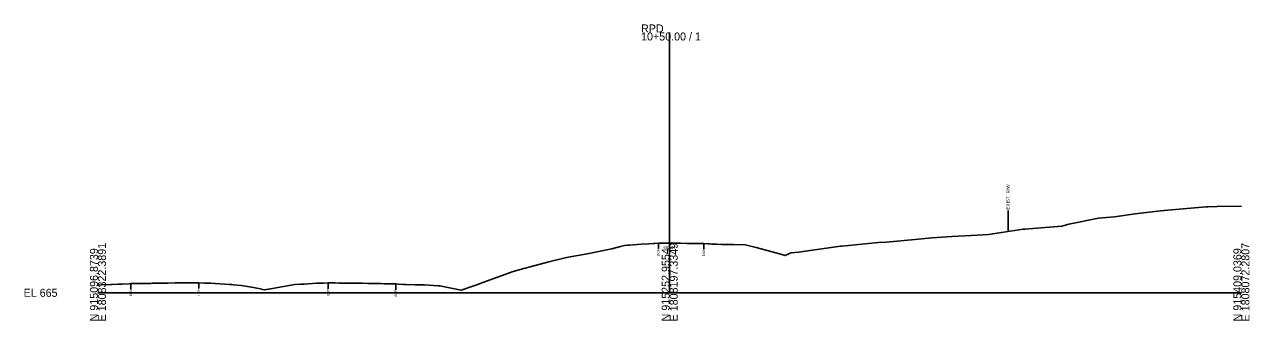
# Model space of a CAD drawing. Extents: x -26 to 403, y -10 to 8517.
# Drawn here: x -25.7 to 402.8, y 990.3 to 1093.9 of the extents above; entities that cross this region are included whole.
import ezdxf

# ---------------------------------------------------------------- set-up
doc = ezdxf.new("R2010")
doc.units = 0
for name, color, linetype in [('Exist Cross Section Cell', 7, 'Continuous'), ('Exist XS Center Line Elevation Label', 7, 'Continuous'), ('Exist XS Ground Line', 7, 'Continuous'), ('Old_Level_10', 7, 'Continuous')]:
    doc.layers.add(name, color=color, linetype=linetype)

msp = doc.modelspace()

# ---------------------------------------------------------------- linework, layer by layer
at = {"layer": 'Exist Cross Section Cell'}
for p, q in [((200, 1000), (200, 1091.12)), ((0, 1000), (200, 1000)), ((200, 1000), (400, 1000))]:
    msp.add_line(p, q, dxfattribs=at)
at = {"layer": 'Exist XS Ground Line'}
msp.add_lwpolyline([(0, 1002.72), (1.41, 1002.79), (4.47, 1002.94), (5, 1002.95), (6.97, 1003.02), (8.46, 1003.06), (10.95, 1003.18), (11.55, 1003.22), (14.93, 1003.27), (16.69, 1003.31), (18.09, 1003.32), (18.47, 1003.32), (18.92, 1003.33), (21.27, 1003.36), (23.06, 1003.38), (23.41, 1003.39), (23.84, 1003.4), (24.49, 1003.41), (26.99, 1003.44), (27.36, 1003.45), (27.66, 1003.45), (29.14, 1003.47), (30.97, 1003.49), (34.06, 1003.51), (34.9, 1003.53), (35.24, 1003.53), (37.3, 1003.43), (38.01, 1003.43), (38.47, 1003.43), (39.46, 1003.41), (40.98, 1003.29), (44.4, 1003.05), (45.99, 1002.93), (46.85, 1002.87), (47.42, 1002.82), (50.11, 1002.62), (52.96, 1002.1), (56.29, 1001.5), (58.13, 1001.05), (60.43, 1001.45), (62.96, 1001.87), (68.88, 1002.88), (70.91, 1003), (72.14, 1003.08), (76.45, 1003.37), (78.96, 1003.39), (80.56, 1003.47), (82.11, 1003.45), (82.95, 1003.44), (84.27, 1003.43), (85.33, 1003.42), (86.92, 1003.4), (88.57, 1003.38), (90.94, 1003.35), (91.52, 1003.34), (92.58, 1003.33), (94.61, 1003.29), (94.96, 1003.28), (96.73, 1003.25), (98.12, 1003.23), (98.95, 1003.22), (100.28, 1003.19), (101.34, 1003.17), (102.05, 1003.15), (102.96, 1003.14), (104.19, 1003.12), (105.01, 1003.04), (106.92, 1002.94), (107.72, 1002.91), (110.94, 1002.82), (113.83, 1002.75), (114.18, 1002.74), (119.04, 1002.47), (119.71, 1002.44), (121.21, 1002.13), (127.08, 1000.94), (131.18, 1002.34), (132.14, 1002.69), (133.67, 1003.23), (144.96, 1007.34), (147.76, 1008.21), (157.77, 1010.83), (163.94, 1012.31), (164.44, 1012.43), (170.59, 1013.58), (179.74, 1015.44), (182.85, 1016.24), (184.25, 1016.56), (185.25, 1016.63), (185.96, 1016.68), (190.08, 1016.99), (192.69, 1017.19), (194.29, 1017.25), (194.8, 1017.29), (196.07, 1017.4), (197.47, 1017.39), (198.09, 1017.39), (198.88, 1017.38), (200, 1017.37), (200.66, 1017.37), (202.89, 1017.35), (203.83, 1017.35), (206.17, 1017.31), (207.06, 1017.29), (207.82, 1017.28), (210.26, 1017.24), (210.68, 1017.24), (212, 1017.22), (213.5, 1017.12), (214.09, 1017.09), (214.8, 1017.06), (216.4, 1016.98), (218.16, 1016.94), (220.22, 1016.9), (221.5, 1016.87), (222.37, 1016.86), (226.4, 1016.79), (230.21, 1015.87), (238.4, 1013.61), (240.45, 1013.02), (241.87, 1013.82), (242.52, 1013.95), (245.19, 1014.27), (247.47, 1014.61), (259.71, 1016.3), (260.28, 1016.37), (262.59, 1016.57), (273.1, 1017.58), (275.7, 1017.73), (285.91, 1018.69), (291.7, 1019.23), (298.72, 1019.69), (307.69, 1020.16), (311.54, 1020.41), (323.68, 1022.24), (324.35, 1022.32), (327.05, 1022.57), (337.16, 1023.37), (339.68, 1024.05), (349.98, 1026.1), (355.67, 1026.6), (362.79, 1027.59), (371.66, 1028.66), (375.61, 1029.02), (387.65, 1030.06), (388.42, 1030.1), (391.51, 1030.17), (400, 1030.37)], dxfattribs=at)
at = {"layer": 'Old_Level_10'}
for p, q in [((318.36, 1028.84), (318.36, 1021.44)), ((196.07, 1017.4), (196.07, 1015.35)), ((212, 1017.22), (212, 1015.17)), ((11.55, 1003.22), (11.55, 1001.17)), ((35.24, 1003.53), (35.24, 1001.48)), ((80.56, 1003.47), (80.56, 1001.42)), ((104.19, 1003.12), (104.19, 1001.07))]:
    msp.add_line(p, q, dxfattribs=at)

# ---------------------------------------------------------------- texts
at = {"layer": 'Exist Cross Section Cell'}
for s, p in [('RPD', (190, 1091.12)), ('10+50.00 / 1', (190, 1088.32)), ('EL 665', (-26, 998.6))]:
    msp.add_text(s, height=2.8, dxfattribs=at).set_placement(p)
for s, p in [('E 1808322.3891', (2.8, 990)), ('E 1808197.3349', (202.8, 990)), ('E 1808072.2807', (402.8, 990)), ('N 915096.8739', (0, 990)), ('N 915252.9554', (200, 990)), ('N 915409.0369', (400, 990))]:
    msp.add_text(s, height=2.8, rotation=90, dxfattribs=at).set_placement(p)
at = {"layer": 'Exist XS Center Line Elevation Label'}
msp.add_text('682.37', height=1, dxfattribs=at).set_placement((197.85, 1015.37))
at = {"layer": 'Old_Level_10'}
for s, height, p in [('EXIST. R/W', 1.181, (318.95, 1029.14)), ('EOP', 0.787, (196.46, 1012.96)), ('EOP', 0.787, (212.39, 1012.77)), ('EOP', 0.787, (11.94, 998.78)), ('EOP', 0.787, (35.64, 999.08)), ('EOP', 0.787, (80.95, 999.02)), ('EOP', 0.787, (104.58, 998.67))]:
    msp.add_text(s, height=height, rotation=90, dxfattribs=at).set_placement(p)

doc.saveas('drawing.dxf')
